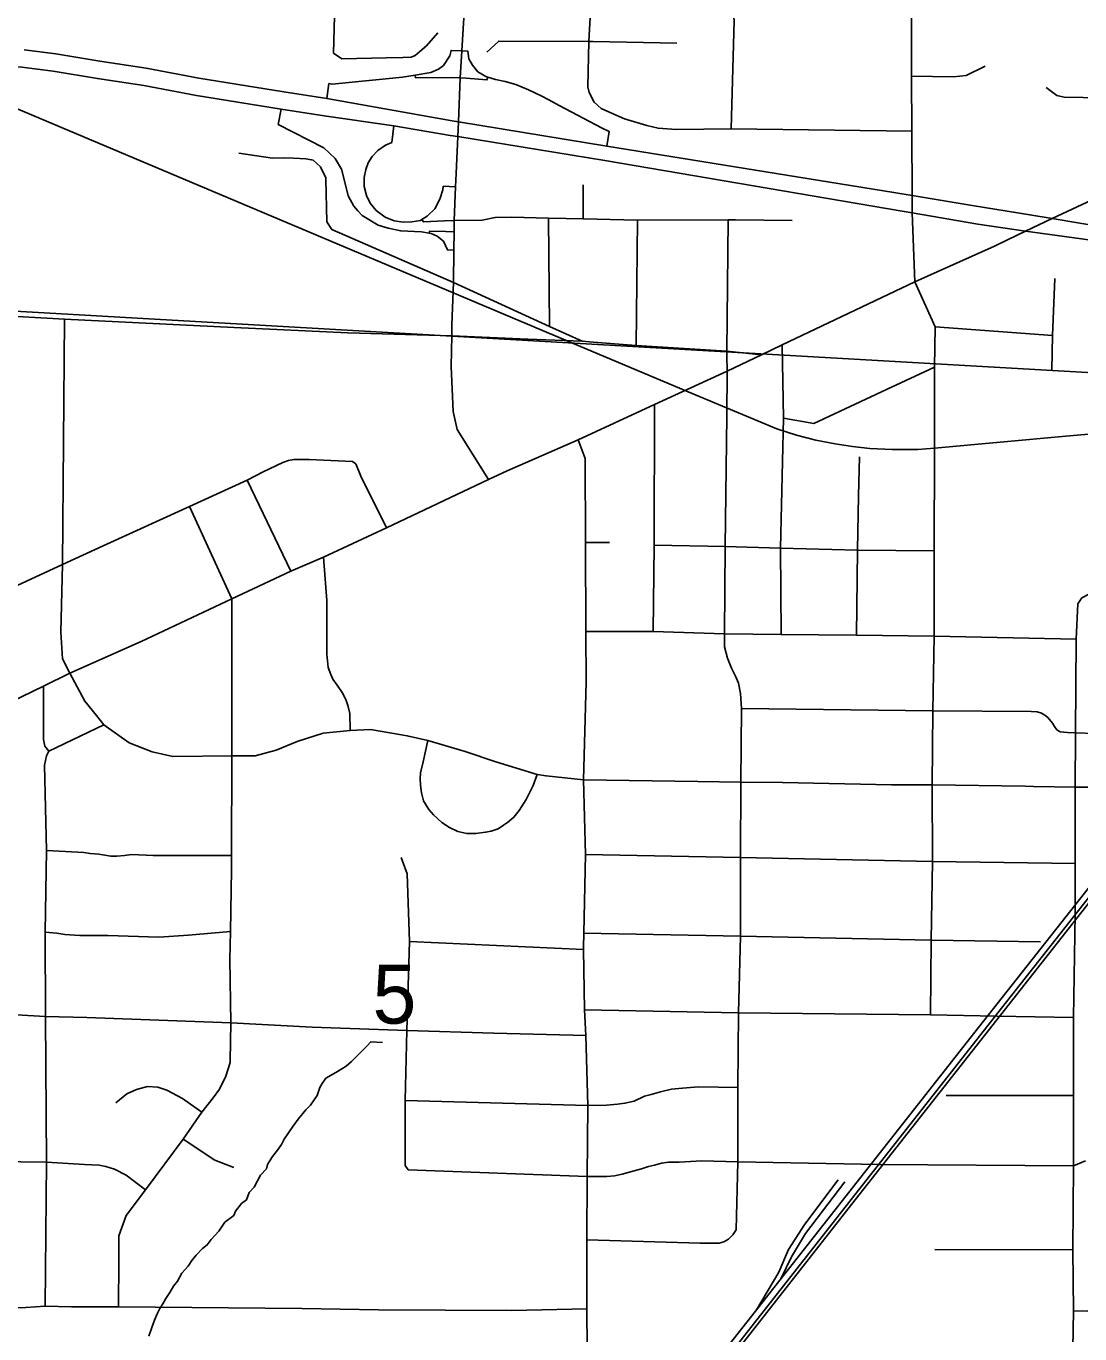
# Model space of a CAD drawing. Extents: x 0 to 34, y 0 to 22.
# Drawn here: x 4.264 to 5.012, y 16.711 to 17.64 of the extents above; entities that cross this region are included whole.
import ezdxf

# ---------------------------------------------------------------- set-up
doc = ezdxf.new("R2010")
doc.units = 0
for name, color, linetype in [('GM_X_City_Street', 7, 'Continuous'), ('GM_X_County_Road', 7, 'Continuous'), ('GM_X_Interchange_Ramps', 7, 'Continuous'), ('GM_X_Minor_River', 7, 'Continuous'), ('GM_X_Rail_Line', 7, 'Continuous'), ('GM_X_Section', 7, 'Continuous'), ('GM_X_Section_Text', 7, 'Continuous'), ('GM_X_State_Route', 7, 'Continuous'), ('GM_X_US_Route', 7, 'Continuous')]:
    doc.layers.add(name, color=color, linetype=linetype)

msp = doc.modelspace()

# ---------------------------------------------------------------- linework, layer by layer
at = {"layer": 'GM_X_City_Street'}
for p, q in [((4.66618, 17.62911), (4.72571, 17.62795)), ((4.65905, 17.5032), (4.65905, 17.5274)), ((4.63509, 17.42683), (4.63458, 17.50374)), ((4.69675, 17.41326), (4.69758, 17.50235)), ((4.76721, 17.50252), (4.80755, 17.502)), ((4.90897, 17.42657), (4.99242, 17.42047)), ((4.45149, 17.25297), (4.42039, 17.31757)), ((4.66065, 17.27331), (4.67789, 17.27331)), ((4.27955, 17.12518), (4.31861, 17.14394)), ((4.97892, 17.1001), (5.00853, 17.09954)), ((4.53568, 16.98995), (4.65934, 16.98435)), ((4.91677, 16.88073), (5.00738, 16.88071)), ((4.90891, 16.77122), (5.00689, 16.77106))]:
    msp.add_line(p, q, dxfattribs=at)
for points in [[(4.89462, 17.45855), (4.89267, 17.50737), (4.89263, 17.51986), (4.89248, 17.56553), (4.89212, 17.60445), (4.89212, 17.64482), (4.89248, 17.67355), (4.89284, 17.73974), (4.89284, 17.82229), (4.89381, 17.89047), (4.8943, 17.96377), (4.89465, 18.02971)], [(4.66693, 17.58602), (4.66332, 17.59285), (4.66242, 17.5969), (4.66321, 17.62917), (4.66602, 17.6811), (4.66723, 17.73919), (4.67114, 17.81318), (4.67381, 17.8916)], [(4.76412, 17.56722), (4.76622, 17.64405), (4.76618, 17.64627), (4.76474, 17.7396), (4.76537, 17.81318), (4.76556, 17.89113)], [(4.48784, 17.61685), (4.48188, 17.62097), (4.48311, 17.67358)], [(4.48784, 17.61685), (4.51913, 17.61766), (4.53113, 17.61789), (4.53702, 17.61813), (4.53984, 17.61931), (4.54313, 17.62213), (4.54784, 17.62613), (4.55584, 17.63531)], [(4.59073, 17.62162), (4.59919, 17.62946), (4.66321, 17.62917), (4.66618, 17.62911)], [(4.89212, 17.60445), (4.92213, 17.60398), (4.93096, 17.60508), (4.94448, 17.61171)], [(4.9878, 17.59653), (4.99553, 17.59073), (5.00076, 17.58964), (5.06839, 17.58844)], [(4.66693, 17.58602), (4.67178, 17.58166), (4.67862, 17.57839), (4.6885, 17.57434), (4.70423, 17.5694), (4.71232, 17.5676), (4.72545, 17.56668), (4.76412, 17.56722), (4.89248, 17.56553)], [(4.41469, 17.5499), (4.43851, 17.54628), (4.446, 17.54665), (4.4535, 17.54628), (4.46212, 17.54591), (4.46624, 17.54516), (4.46737, 17.54478), (4.47264, 17.54014)], [(4.47718, 17.50118), (4.47638, 17.53141), (4.47638, 17.53225), (4.47264, 17.54014)], [(4.96037, 17.48824), (4.9733, 17.49455), (4.99221, 17.50339), (5.0637, 17.5368)], [(4.47718, 17.50118), (4.48059, 17.4956), (4.56697, 17.45805), (4.63509, 17.42683), (4.65838, 17.4164)], [(4.56745, 17.50202), (4.58726, 17.50235), (4.59666, 17.50408), (4.60849, 17.50443), (4.63458, 17.50374), (4.65905, 17.5032), (4.69758, 17.50235), (4.76217, 17.50258), (4.76721, 17.50252)], [(4.76114, 17.40602), (4.76106, 17.40931), (4.76217, 17.50258)], [(4.23751, 17.15294), (4.27584, 17.17136), (4.29456, 17.18062), (4.34534, 17.20306), (4.40957, 17.23325), (4.45149, 17.25297), (4.47463, 17.26287), (4.50928, 17.27904), (4.51945, 17.28385), (4.5919, 17.31813), (4.60503, 17.32434), (4.65553, 17.34637), (4.70967, 17.37129), (4.7614, 17.39508), (4.78579, 17.40669), (4.8003, 17.41379), (4.89462, 17.45855), (4.95112, 17.48373), (4.96037, 17.48824)], [(4.99198, 17.3961), (4.99242, 17.42047), (4.99394, 17.46094)], [(3.68615, 17.45787), (3.70636, 17.45718), (3.76567, 17.45514), (3.81033, 17.45332), (3.83666, 17.45225), (3.89969, 17.44919), (3.90794, 17.44868), (3.94954, 17.44801), (3.97884, 17.4465), (4.00359, 17.44589), (4.04897, 17.4433), (4.06932, 17.44272), (4.13405, 17.43905), (4.18594, 17.43688), (4.24012, 17.43473), (4.2908, 17.43188), (4.41123, 17.4261), (4.49199, 17.42222), (4.5659, 17.42002)], [(4.90563, 16.93803), (4.90614, 16.99097), (4.90712, 17.04673), (4.90684, 17.10134), (4.90734, 17.15388), (4.90826, 17.20695), (4.90826, 17.26739), (4.90845, 17.33965), (4.90845, 17.39777), (4.90897, 17.42657), (4.89462, 17.45855)], [(4.29456, 17.18062), (4.28946, 17.19069), (4.28819, 17.20975), (4.28939, 17.25777), (4.2908, 17.43188)], [(4.5659, 17.42002), (4.6198, 17.41784), (4.65838, 17.4164), (4.66625, 17.41575)], [(4.66625, 17.41575), (4.69675, 17.41326), (4.76106, 17.40931), (4.78579, 17.40669)], [(4.8003, 17.41379), (4.80134, 17.36167), (4.79924, 17.26944), (4.79957, 17.208)], [(4.7653, 16.78167), (4.76767, 16.78522), (4.76883, 16.83353), (4.76884, 16.88632), (4.76948, 16.93943), (4.77077, 16.99367), (4.77077, 17.04973), (4.77098, 17.10326), (4.77155, 17.15543), (4.77083, 17.16618), (4.7694, 17.17335), (4.76725, 17.17837), (4.76438, 17.1841), (4.76151, 17.19126), (4.75936, 17.19915), (4.75936, 17.20846), (4.76004, 17.27046), (4.76105, 17.36318), (4.7614, 17.39508), (4.76114, 17.40602)], [(4.80134, 17.36167), (4.82277, 17.35795), (4.87451, 17.38211), (4.90845, 17.39777)], [(4.70888, 17.21013), (4.70957, 17.27138), (4.70967, 17.37129)], [(4.65943, 17.10488), (4.66113, 17.17411), (4.66104, 17.21021), (4.66065, 17.27331), (4.6604, 17.33307), (4.65553, 17.34637)], [(3.73239, 17.01647), (3.76227, 17.01563), (3.7734, 17.01902), (3.84774, 17.05359), (3.84989, 17.0546), (3.91882, 17.08684), (4.03815, 17.14097), (4.13425, 17.18633), (4.18379, 17.20897), (4.23809, 17.23396), (4.28939, 17.25777), (4.31831, 17.27103), (4.37951, 17.29903), (4.42039, 17.31757), (4.43186, 17.32366), (4.44581, 17.33025), (4.44975, 17.33157), (4.45369, 17.33222), (4.46453, 17.33222), (4.49541, 17.33091), (4.49756, 17.32932), (4.50132, 17.32058), (4.51945, 17.28385)], [(4.85322, 17.20759), (4.85385, 17.26789), (4.8547, 17.30644), (4.8553, 17.33426)], [(4.32917, 16.73055), (4.32934, 16.76328), (4.32934, 16.77301), (4.32934, 16.78103), (4.33449, 16.79534), (4.34823, 16.81366), (4.37513, 16.84972), (4.38821, 16.86879), (4.39631, 16.87891), (4.40089, 16.88521), (4.40547, 16.89437), (4.40833, 16.9041), (4.40833, 16.90525), (4.4089, 16.93215), (4.40829, 16.97729), (4.40865, 16.99702), (4.40943, 17.04082), (4.40944, 17.05117), (4.4095, 17.12195), (4.40957, 17.23325), (4.37951, 17.29903)], [(4.70957, 17.27138), (4.76004, 17.27046), (4.79924, 17.26944), (4.85385, 17.26789), (4.90826, 17.26739)], [(4.47704, 17.20486), (4.47704, 17.23215), (4.47463, 17.26287)], [(5.00871, 17.13822), (5.00916, 17.20476), (5.01039, 17.22991), (5.0132, 17.234), (5.02507, 17.24021), (5.03758, 17.24415), (5.05216, 17.24874), (5.05621, 17.25106), (5.05783, 17.25198), (5.06447, 17.25734)], [(4.66104, 17.21021), (4.70888, 17.21013), (4.75936, 17.20846), (4.79957, 17.208), (4.85322, 17.20759), (4.90826, 17.20695), (5.00916, 17.20476)], [(4.49362, 17.13993), (4.49338, 17.15185), (4.49232, 17.15682), (4.49054, 17.1618), (4.48805, 17.16677), (4.4845, 17.1721), (4.4813, 17.17637), (4.47988, 17.17956), (4.4781, 17.18454), (4.47704, 17.19413), (4.47704, 17.20486)], [(4.29456, 17.18062), (4.30528, 17.16074), (4.31348, 17.15041), (4.31861, 17.14394), (4.33679, 17.1311), (4.35302, 17.12473), (4.36769, 17.12127), (4.4095, 17.12195), (4.41835, 17.12195)], [(4.27702, 16.73104), (4.27799, 16.8332), (4.27738, 16.93669), (4.27713, 16.99672), (4.27795, 17.05453), (4.27664, 17.11531), (4.27808, 17.12178), (4.27955, 17.12518), (4.27686, 17.12878), (4.27597, 17.13334), (4.27584, 17.17136)], [(4.77155, 17.15543), (4.90734, 17.15388), (4.9772, 17.15331), (4.9815, 17.15302), (4.98465, 17.15216), (4.98694, 17.15073), (4.98894, 17.14901), (4.99238, 17.145), (4.99381, 17.14271), (4.99553, 17.14042), (4.99782, 17.13899), (5.00298, 17.13841), (5.00871, 17.13822), (5.06269, 17.13641)], [(4.41835, 17.12195), (4.42622, 17.12195), (4.44105, 17.1258), (4.45598, 17.13193), (4.47438, 17.138), (4.49362, 17.13993), (4.50799, 17.14047), (4.52186, 17.13808), (4.53412, 17.13608), (4.5488, 17.13274), (4.57541, 17.12496), (4.59702, 17.11767), (4.62641, 17.1087), (4.63273, 17.10755), (4.65943, 17.10488)], [(4.99735, 16.46149), (5.00503, 16.51316), (5.00704, 16.5445), (5.00695, 16.6363), (5.00634, 16.67418), (5.00729, 16.72763), (5.00689, 16.77106), (5.00732, 16.83058), (5.00738, 16.88071), (5.00738, 16.93612), (5.00849, 17.00934), (5.00837, 17.04545), (5.00853, 17.09954), (5.0087, 17.13728), (5.00871, 17.13822)], [(4.5488, 17.13274), (4.54539, 17.11762), (4.54358, 17.10979), (4.5433, 17.10569), (4.54358, 17.10101), (4.54429, 17.09552), (4.54579, 17.0899), (4.54961, 17.08367), (4.55282, 17.08005), (4.55865, 17.07463), (4.56428, 17.07101), (4.5701, 17.0682), (4.57653, 17.06659), (4.58276, 17.06659), (4.58979, 17.0676), (4.59381, 17.0684), (4.59883, 17.07001), (4.60245, 17.07262), (4.60546, 17.07443), (4.60988, 17.07824), (4.6137, 17.08306), (4.61872, 17.0909), (4.62354, 17.10075), (4.62641, 17.1087)], [(4.53689, 16.4661), (4.53929, 16.47728), (4.55073, 16.5023), (4.57203, 16.53584), (4.59597, 16.5667), (4.61954, 16.59339), (4.65058, 16.63744), (4.65808, 16.65345), (4.66209, 16.67247), (4.66159, 16.72904), (4.66159, 16.77809), (4.66201, 16.82322), (4.66248, 16.8735), (4.661, 16.92318), (4.66004, 16.94142), (4.65934, 16.98435), (4.65932, 16.98581), (4.65956, 16.99589), (4.66076, 17.05179), (4.65943, 17.10488)], [(4.65943, 17.10488), (4.74042, 17.10362), (4.77098, 17.10326), (4.80075, 17.10297), (4.87803, 17.10134), (4.90684, 17.10134), (4.973, 17.10021), (4.97892, 17.1001)], [(5.00853, 17.09954), (5.0409, 17.09961), (5.07054, 17.09884), (5.07752, 17.09866)], [(4.27795, 17.05453), (4.29145, 17.0539), (4.30445, 17.05326), (4.30911, 17.05245), (4.31521, 17.05197), (4.32372, 17.05068), (4.3279, 17.05052), (4.33336, 17.05117), (4.3385, 17.05181), (4.35374, 17.05117), (4.37911, 17.05101), (4.40944, 17.05117)], [(4.66076, 17.05179), (4.77077, 17.04973), (4.90712, 17.04673), (5.00837, 17.04545)], [(4.53488, 16.82777), (4.53279, 16.83091), (4.53279, 16.87697), (4.53384, 16.92677), (4.53568, 16.98995), (4.53423, 17.03817), (4.52992, 17.04968)], [(4.27713, 16.99672), (4.28536, 16.99583), (4.291, 16.99494), (4.30167, 16.99435), (4.32154, 16.99435), (4.35773, 16.99316), (4.37892, 16.99454), (4.40865, 16.99702)], [(4.65956, 16.99589), (4.77077, 16.99367), (4.90614, 16.99097), (4.98385, 16.98975)], [(3.88339, 16.95144), (3.93998, 16.9481), (3.97993, 16.94801), (4.06295, 16.94409), (4.11267, 16.94243), (4.16841, 16.94025), (4.22277, 16.93976), (4.27738, 16.93669), (4.30671, 16.93597), (4.4089, 16.93215), (4.46669, 16.92919), (4.53384, 16.92677), (4.59562, 16.92482), (4.661, 16.92318)], [(4.66004, 16.94142), (4.76948, 16.93943), (4.90563, 16.93803), (4.95289, 16.937), (5.00738, 16.93612)], [(4.32716, 16.87549), (4.33503, 16.88179), (4.34186, 16.88494), (4.34972, 16.88704), (4.35707, 16.88651), (4.36337, 16.88441), (4.37454, 16.87849), (4.38821, 16.86879)], [(4.53279, 16.87697), (4.66248, 16.8735), (4.67566, 16.87387), (4.68341, 16.87448), (4.68868, 16.8751), (4.69519, 16.87665), (4.70262, 16.88006), (4.70727, 16.8813), (4.7141, 16.88316), (4.72184, 16.88502), (4.72959, 16.88595), (4.74105, 16.88688), (4.76884, 16.88632)], [(4.37513, 16.84972), (4.39755, 16.83475), (4.41093, 16.82949)], [(4.22277, 16.83404), (4.27799, 16.8332), (4.30489, 16.83171), (4.3153, 16.83109), (4.32003, 16.83014), (4.32634, 16.82825), (4.33454, 16.82414), (4.34823, 16.81366)], [(4.53488, 16.82777), (4.66201, 16.82322), (4.67269, 16.82322), (4.676, 16.82322), (4.68145, 16.82361), (4.6869, 16.82478), (4.69274, 16.82634), (4.70052, 16.82867), (4.70558, 16.83023), (4.70967, 16.8312), (4.71473, 16.83256), (4.71979, 16.83334), (4.72719, 16.83334), (4.74334, 16.83412), (4.76883, 16.83353), (4.86928, 16.83161), (5.00732, 16.83058), (5.01585, 16.8342)], [(4.66159, 16.77809), (4.74211, 16.77582), (4.74923, 16.77582), (4.75343, 16.77582), (4.75562, 16.77582), (4.75909, 16.77673), (4.7622, 16.77856), (4.7653, 16.78167)], [(4.02907, 16.7001), (4.03351, 16.70704), (4.03767, 16.71093), (4.04156, 16.71426), (4.04656, 16.71704), (4.051, 16.71926), (4.05711, 16.7212), (4.06822, 16.72259), (4.10265, 16.72371), (4.11098, 16.72454), (4.13653, 16.72426), (4.1736, 16.72546), (4.22159, 16.72834), (4.24613, 16.72956), (4.26343, 16.73006), (4.27702, 16.73104), (4.2958, 16.73055), (4.32917, 16.73055), (4.4594, 16.72932), (4.51383, 16.72847), (4.60854, 16.72804), (4.66159, 16.72904)], [(5.00729, 16.72763), (5.06792, 16.72638), (5.12856, 16.72514), (5.18783, 16.72263)]]:
    msp.add_lwpolyline(points, dxfattribs=at)
at = {"layer": 'GM_X_County_Road'}
for points in [[(4.57592, 17.96789), (4.58015, 17.93952), (4.5831, 17.91071), (4.58363, 17.89219), (4.58063, 17.82758), (4.58, 17.81402), (4.57856, 17.76028), (4.57788, 17.73464), (4.57659, 17.68146), (4.5729, 17.62248), (4.57182, 17.60338), (4.57062, 17.57213), (4.57042, 17.56673), (4.57016, 17.56159), (4.56885, 17.53553)], [(4.56885, 17.53553), (4.56837, 17.52588), (4.56745, 17.50202), (4.56755, 17.49399), (4.56733, 17.48099), (4.56697, 17.45805), (4.56589, 17.42784), (4.5659, 17.42002)], [(4.5659, 17.42002), (4.56526, 17.39832), (4.56682, 17.36632), (4.56973, 17.35353), (4.5919, 17.31813)]]:
    msp.add_lwpolyline(points, dxfattribs=at)
at = {"layer": 'GM_X_Interchange_Ramps'}
for points in [[(4.5729, 17.62248), (4.56532, 17.62288), (4.56438, 17.6189), (4.55985, 17.6121), (4.55639, 17.60942), (4.551, 17.60708), (4.53979, 17.60524), (4.5309, 17.60377), (4.48079, 17.59878), (4.47851, 17.59929), (4.47701, 17.58879)], [(4.59137, 17.60388), (4.58986, 17.60437), (4.58418, 17.60772), (4.58039, 17.61236), (4.57788, 17.61679), (4.57721, 17.6222), (4.5729, 17.62248)], [(4.57182, 17.60338), (4.56658, 17.60361), (4.54009, 17.60343), (4.53979, 17.60524)], [(4.59137, 17.60388), (4.59073, 17.6019), (4.57592, 17.6032), (4.57182, 17.60338)], [(4.63463, 17.58775), (4.62937, 17.59063), (4.62022, 17.59493), (4.61128, 17.59852), (4.60377, 17.60087), (4.59673, 17.60214), (4.59137, 17.60388)], [(4.44472, 17.58114), (4.44249, 17.57022), (4.47491, 17.55368), (4.48295, 17.54606), (4.48743, 17.53847), (4.48937, 17.5311), (4.4922, 17.5196), (4.49627, 17.51232), (4.49918, 17.50898)], [(4.67597, 17.55494), (4.67749, 17.56531), (4.67249, 17.56763), (4.642, 17.58372), (4.63463, 17.58775)], [(4.56837, 17.52588), (4.55968, 17.52632), (4.55937, 17.52385), (4.55724, 17.51722), (4.55367, 17.51038), (4.54826, 17.50504), (4.54461, 17.5028), (4.54354, 17.50215), (4.53734, 17.50119), (4.53118, 17.50082), (4.52496, 17.50179), (4.51854, 17.50436), (4.512, 17.50925), (4.50785, 17.51445), (4.5052, 17.51984), (4.50364, 17.52624), (4.50353, 17.53257), (4.50465, 17.53833), (4.5065, 17.54298), (4.50934, 17.54752), (4.51333, 17.55181), (4.51866, 17.55552), (4.52322, 17.55747), (4.52454, 17.56936)], [(4.49918, 17.50898), (4.50208, 17.50565), (4.51345, 17.49869), (4.52053, 17.49648), (4.52955, 17.49462), (4.54418, 17.49408), (4.54962, 17.4931)], [(4.56745, 17.50202), (4.56062, 17.50191), (4.54568, 17.50106), (4.54461, 17.5028)], [(4.54962, 17.4931), (4.54986, 17.49446), (4.56157, 17.49427), (4.56755, 17.49399)], [(4.54962, 17.4931), (4.5512, 17.49281), (4.55553, 17.49086), (4.56002, 17.48725), (4.56266, 17.48116), (4.56733, 17.48099)]]:
    msp.add_lwpolyline(points, dxfattribs=at)
at = {"layer": 'GM_X_Minor_River'}
for points in [[(4.40041, 16.78423), (4.40475, 16.79059), (4.41095, 16.79537), (4.41217, 16.79839), (4.41649, 16.80398), (4.41997, 16.80656), (4.422, 16.81183), (4.42552, 16.81554), (4.42992, 16.82417), (4.43421, 16.82863), (4.43504, 16.83165), (4.4386, 16.83726), (4.44214, 16.84174), (4.4449, 16.84585), (4.44689, 16.8496), (4.45282, 16.85857), (4.45675, 16.8638), (4.46224, 16.87051), (4.46536, 16.87385), (4.46812, 16.87758), (4.47009, 16.88057), (4.47213, 16.88622), (4.47373, 16.88923), (4.47648, 16.89296), (4.48342, 16.89697), (4.48767, 16.89952), (4.49076, 16.90135), (4.49464, 16.90467), (4.49972, 16.90987), (4.50518, 16.91543), (4.5083, 16.91878), (4.51665, 16.91819)], [(4.35066, 16.70983), (4.35271, 16.71586), (4.35474, 16.72113), (4.35676, 16.72602), (4.35837, 16.7294), (4.36073, 16.73276), (4.36273, 16.73651), (4.36549, 16.74063), (4.36826, 16.74512), (4.37102, 16.74885), (4.3742, 16.75447), (4.3785, 16.75931), (4.38126, 16.76342), (4.3844, 16.76714), (4.3887, 16.77198), (4.39218, 16.77455), (4.39494, 16.77829), (4.40041, 16.78423)]]:
    msp.add_lwpolyline(points, dxfattribs=at)
at = {"layer": 'GM_X_Rail_Line'}
for points in [[(5.06095, 17.35408), (5.0018, 17.3488), (4.90866, 17.3403), (4.89685, 17.33947), (4.87841, 17.33937), (4.86266, 17.3402), (4.85033, 17.34154), (4.83801, 17.34351), (4.82423, 17.3461), (4.81055, 17.34962), (4.79657, 17.35408), (4.73638, 17.37925), (4.63464, 17.42192), (4.11228, 17.64251), (4.03964, 17.67294), (4.03082, 17.67523), (4.02123, 17.67644), (4.01059, 17.67659), (3.99963, 17.67568), (3.98145, 17.67223), (3.94441, 17.66518), (3.87792, 17.65271), (3.74009, 17.62517)], [(4.35425, 16.13582), (4.36394, 16.1559), (4.37306, 16.17358), (4.37894, 16.18451), (4.38539, 16.19657), (4.3962, 16.21566), (4.40265, 16.22618), (4.41023, 16.23895), (4.41936, 16.25257), (4.43182, 16.27161), (4.44445, 16.29), (4.45779, 16.30811), (4.46957, 16.32325), (4.70422, 16.62171), (4.84778, 16.80473), (4.95343, 16.93934), (5.08034, 17.10039), (5.11908, 17.14989), (5.18416, 17.23304), (5.30267, 17.38345), (5.42591, 17.54069), (5.4633, 17.58845)], [(5.14205, 17.18746), (5.13852, 17.18175), (5.12841, 17.16794), (4.93975, 16.92898), (4.77527, 16.71961), (4.68229, 16.60148)], [(4.35651, 16.13478), (4.36616, 16.15479), (4.37526, 16.17242), (4.38113, 16.18333), (4.38757, 16.19537), (4.39834, 16.2144), (4.40478, 16.22489), (4.41234, 16.23762), (4.42143, 16.2512), (4.43389, 16.27023), (4.44648, 16.28856), (4.45977, 16.30661), (4.47152, 16.32172), (4.70618, 16.62018), (4.84974, 16.8032), (4.95538, 16.9378), (5.08229, 17.09885)], [(4.78217, 16.7284), (4.79795, 16.75512), (4.80486, 16.77115), (4.81645, 16.78915), (4.84012, 16.82071)], [(4.79952, 16.75047), (4.80708, 16.76597), (4.81694, 16.78274), (4.84481, 16.81924)]]:
    msp.add_lwpolyline(points, dxfattribs=at)
at = {"layer": 'GM_X_Section'}
for points in [[(4.05276, 18.48869), (5.03965, 18.48463), (5.04609, 17.39252), (4.04846, 17.44949)], [(4.04846, 17.44949), (5.04609, 17.39252), (5.01599, 16.47353), (4.01128, 16.47685)]]:
    msp.add_lwpolyline(points, close=True, dxfattribs=at)
at = {"layer": 'GM_X_State_Route'}
for points in [[(3.74647, 17.51448), (3.77597, 17.52056), (3.81874, 17.52796), (3.85691, 17.53437), (3.92599, 17.54605), (3.98308, 17.55527), (4.02502, 17.56283), (4.06055, 17.56925), (4.09049, 17.57681), (4.115, 17.58455), (4.13869, 17.59228), (4.15826, 17.59836), (4.17521, 17.60297), (4.18368, 17.60553), (4.18771, 17.60675), (4.20416, 17.61004), (4.22143, 17.61251), (4.23673, 17.61235), (4.26042, 17.61103), (4.28279, 17.60807), (4.31421, 17.60281), (4.34711, 17.59787), (4.38445, 17.5908), (4.44472, 17.58114)], [(4.44472, 17.58114), (4.47525, 17.57649), (4.52454, 17.56936)], [(4.52454, 17.56936), (4.56457, 17.5625), (4.57016, 17.56159), (4.67445, 17.54457), (4.88567, 17.50856), (4.89267, 17.50737), (4.93926, 17.49947), (4.9733, 17.49455), (4.97848, 17.49384)], [(4.97848, 17.49384), (5.0665, 17.48174), (5.07254, 17.48091), (5.13349, 17.47352)]]:
    msp.add_lwpolyline(points, dxfattribs=at)
at = {"layer": 'GM_X_US_Route'}
for points in [[(4.26218, 17.62334), (4.28455, 17.62038), (4.31597, 17.61511), (4.34887, 17.61018), (4.38621, 17.60311), (4.44648, 17.59345), (4.47701, 17.58879), (4.56609, 17.57287), (4.57062, 17.57213), (4.67597, 17.55494), (4.87975, 17.52204), (4.89263, 17.51986), (4.93535, 17.51266), (4.97631, 17.50608), (4.99221, 17.50339), (5.03142, 17.49674)], [(3.74647, 17.51448), (3.77597, 17.52056), (3.81874, 17.52796), (3.85691, 17.53437), (3.92599, 17.54605), (3.98308, 17.55527), (4.02502, 17.56283), (4.06055, 17.56925), (4.09049, 17.57681), (4.115, 17.58455), (4.13869, 17.59228), (4.15826, 17.59836), (4.17521, 17.60297), (4.18368, 17.60553), (4.18771, 17.60675), (4.20416, 17.61004), (4.22143, 17.61251), (4.23673, 17.61235), (4.26042, 17.61103), (4.28279, 17.60807), (4.31421, 17.60281), (4.34711, 17.59787), (4.38445, 17.5908), (4.44472, 17.58114)], [(4.44472, 17.58114), (4.47525, 17.57649), (4.52454, 17.56936)], [(4.52454, 17.56936), (4.56457, 17.5625), (4.57016, 17.56159), (4.67445, 17.54457), (4.88567, 17.50856), (4.89267, 17.50737), (4.93926, 17.49947), (4.9733, 17.49455), (4.97848, 17.49384)], [(4.97848, 17.49384), (5.0665, 17.48174), (5.07254, 17.48091), (5.13349, 17.47352)]]:
    msp.add_lwpolyline(points, dxfattribs=at)

# ---------------------------------------------------------------- texts
at = {"layer": 'GM_X_Section_Text'}
msp.add_text('5', height=0.04186, rotation=0.00001, dxfattribs=at).set_placement((4.50952, 16.93169))

doc.saveas('drawing.dxf')
